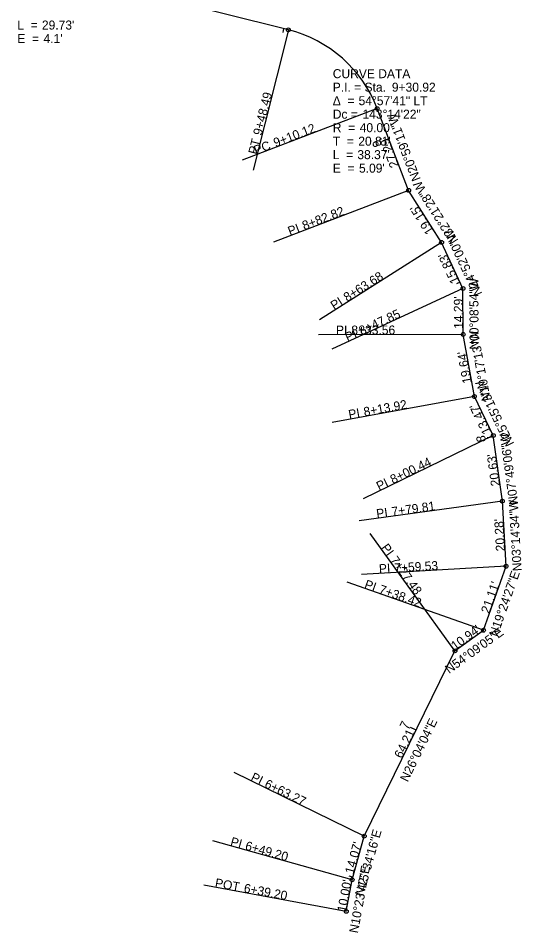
# Model space of a CAD drawing. Extents: x 1922742 to 1923057, y 359346 to 359870.
# Drawn here: x 1922900.4 to 1923056.9, y 359346.4 to 359631 of the extents above; entities that cross this region are included whole.
import ezdxf

# ---------------------------------------------------------------- set-up
doc = ezdxf.new("R2010")
doc.units = 0
for name, color, linetype in [('_CIVIL_CONSTRUCTION', 7, 'Continuous'), ('DT_P_Graded_Shoulder', 7, 'Continuous'), ('DT_P_Tie', 7, 'Continuous'), ('MD_P_ACB_B', 7, 'Continuous'), ('MD_P_ACSC_B', 7, 'Continuous'), ('MD_P_ACSC_T', 7, 'Continuous'), ('MD_P_AGB_T', 7, 'Continuous'), ('MD_P_AGST_B', 7, 'Continuous'), ('MD_P_AGST_T', 7, 'Continuous'), ('MD_P_GRADE_BREAK', 7, 'Continuous'), ('MD_P_PGL', 7, 'Continuous'), ('MD_P_Surface_Asphalt_Concrete_Base', 7, 'Continuous'), ('MD_X_XGL', 7, 'Continuous'), ('PV_P_EOP', 7, 'Continuous'), ('PV_P_Shoulder', 7, 'Continuous')]:
    doc.layers.add(name, color=color, linetype=linetype)

msp = doc.modelspace()

# ---------------------------------------------------------------- linework, layer by layer
at = {"layer": '_CIVIL_CONSTRUCTION'}
for p, q in [((1922984.36, 359627.36), (1922910.59, 359645.83)), ((1923021.77, 359577.4), (1923011.99, 359602.88)), ((1923032.01, 359561.23), (1923021.77, 359577.4)), ((1923038.67, 359546.87), (1923032.01, 359561.23)), ((1923038.71, 359532.58), (1923038.67, 359546.87)), ((1923042.21, 359513.25), (1923038.71, 359532.58)), ((1923048.1, 359501.13), (1923042.21, 359513.25)), ((1923050.91, 359480.69), (1923048.1, 359501.13)), ((1923052.06, 359460.45), (1923050.91, 359480.69)), ((1923045.04, 359440.54), (1923052.06, 359460.45)), ((1923036.17, 359434.13), (1923045.04, 359440.54)), ((1923007.96, 359376.45), (1923036.17, 359434.13)), ((1923004.18, 359362.9), (1923007.96, 359376.45)), ((1923002.38, 359353.06), (1923004.18, 359362.9))]:
    msp.add_line(p, q, dxfattribs=at)
msp.add_arc((1922974.65, 359588.56), 40, 20.9863, 75.9476, dxfattribs=at)
at = {"layer": 'MD_P_AGB_T'}
for p, q in [((1922984.36, 359627.36), (1922973.43, 359583.71)), ((1923011.99, 359602.88), (1922969.98, 359586.77)), ((1923021.77, 359577.4), (1922979.75, 359561.29)), ((1923032.01, 359561.23), (1922994, 359537.14)), ((1923038.67, 359546.87), (1922997.84, 359527.95)), ((1923038.71, 359532.58), (1922993.71, 359532.46)), ((1923042.21, 359513.25), (1922997.94, 359505.22)), ((1923048.1, 359501.13), (1923007.63, 359481.46)), ((1923050.91, 359480.69), (1923006.33, 359474.57)), ((1923036.17, 359434.13), (1923009.82, 359470.6)), ((1923052.06, 359460.45), (1923007.13, 359457.9)), ((1923045.04, 359440.54), (1923002.6, 359455.49)), ((1923007.96, 359376.45), (1922967.54, 359396.23)), ((1923004.18, 359362.9), (1922960.83, 359374.98)), ((1923002.38, 359353.06), (1922958.12, 359361.18))]:
    msp.add_line(p, q, dxfattribs=at)
for centre in [(1922984.36, 359627.36), (1923011.99, 359602.88), (1923021.77, 359577.4), (1923032.01, 359561.23), (1923038.67, 359546.87), (1923038.71, 359532.58), (1923042.21, 359513.25), (1923048.1, 359501.13), (1923050.91, 359480.69), (1923052.06, 359460.45), (1923045.04, 359440.54), (1923036.17, 359434.13), (1923007.96, 359376.45), (1923004.18, 359362.9), (1923002.38, 359353.06)]:
    msp.add_circle(centre, 0.6, dxfattribs=at)
at = {"layer": 'MD_P_AGST_B'}
for p, q in [((1922984.36, 359627.36), (1922973.43, 359583.71)), ((1923011.99, 359602.88), (1922969.98, 359586.77)), ((1923021.77, 359577.4), (1922979.75, 359561.29)), ((1923032.01, 359561.23), (1922994, 359537.14)), ((1923038.67, 359546.87), (1922997.84, 359527.95)), ((1923038.71, 359532.58), (1922993.71, 359532.46)), ((1923042.21, 359513.25), (1922997.94, 359505.22)), ((1923048.1, 359501.13), (1923007.63, 359481.46)), ((1923050.91, 359480.69), (1923006.33, 359474.57)), ((1923036.17, 359434.13), (1923009.82, 359470.6)), ((1923052.06, 359460.45), (1923007.13, 359457.9)), ((1923045.04, 359440.54), (1923002.6, 359455.49)), ((1923007.96, 359376.45), (1922967.54, 359396.23)), ((1923004.18, 359362.9), (1922960.83, 359374.98)), ((1923002.38, 359353.06), (1922958.12, 359361.18))]:
    msp.add_line(p, q, dxfattribs=at)
for centre in [(1922984.36, 359627.36), (1923011.99, 359602.88), (1923021.77, 359577.4), (1923032.01, 359561.23), (1923038.67, 359546.87), (1923038.71, 359532.58), (1923042.21, 359513.25), (1923048.1, 359501.13), (1923050.91, 359480.69), (1923052.06, 359460.45), (1923045.04, 359440.54), (1923036.17, 359434.13), (1923007.96, 359376.45), (1923004.18, 359362.9), (1923002.38, 359353.06)]:
    msp.add_circle(centre, 0.6, dxfattribs=at)
at = {"layer": 'MD_P_GRADE_BREAK'}
for p, q in [((1922984.36, 359627.36), (1922973.43, 359583.71)), ((1923011.99, 359602.88), (1922969.98, 359586.77)), ((1923021.77, 359577.4), (1922979.75, 359561.29)), ((1923032.01, 359561.23), (1922994, 359537.14)), ((1923038.67, 359546.87), (1922997.84, 359527.95)), ((1923038.71, 359532.58), (1922993.71, 359532.46)), ((1923042.21, 359513.25), (1922997.94, 359505.22)), ((1923048.1, 359501.13), (1923007.63, 359481.46)), ((1923050.91, 359480.69), (1923006.33, 359474.57)), ((1923036.17, 359434.13), (1923009.82, 359470.6)), ((1923052.06, 359460.45), (1923007.13, 359457.9)), ((1923045.04, 359440.54), (1923002.6, 359455.49)), ((1923007.96, 359376.45), (1922967.54, 359396.23)), ((1923004.18, 359362.9), (1922960.83, 359374.98)), ((1923002.38, 359353.06), (1922958.12, 359361.18))]:
    msp.add_line(p, q, dxfattribs=at)
for centre in [(1922984.36, 359627.36), (1923011.99, 359602.88), (1923021.77, 359577.4), (1923032.01, 359561.23), (1923038.67, 359546.87), (1923038.71, 359532.58), (1923042.21, 359513.25), (1923048.1, 359501.13), (1923050.91, 359480.69), (1923052.06, 359460.45), (1923045.04, 359440.54), (1923036.17, 359434.13), (1923007.96, 359376.45), (1923004.18, 359362.9), (1923002.38, 359353.06)]:
    msp.add_circle(centre, 0.6, dxfattribs=at)
at = {"layer": 'MD_P_Surface_Asphalt_Concrete_Base'}
for p, q in [((1923015.62, 359593.44), (1923014.49, 359593.01)), ((1923048.16, 359500.69), (1923046.98, 359500.53)), ((1923024.1, 359409.44), (1923023.02, 359409.97))]:
    msp.add_line(p, q, dxfattribs=at)
at = {"layer": 'MD_X_XGL'}
for p, q in [((1922982.89, 359627.73), (1922982.6, 359626.57)), ((1923015.62, 359593.44), (1923013.75, 359592.72)), ((1923037.77, 359548.82), (1923036.68, 359548.32)), ((1923048.16, 359500.69), (1923046.18, 359500.42)), ((1923048.89, 359451.46), (1923047.76, 359451.86)), ((1923024.1, 359409.44), (1923022.3, 359410.32)), ((1923004.4, 359363.67), (1923003.24, 359363.99))]:
    msp.add_line(p, q, dxfattribs=at)

# ---------------------------------------------------------------- texts
at = {"layer": 'DT_P_Graded_Shoulder'}
for s, p in [('L  = ', (1922900.06, 359627.45)), ("29.73'", (1922907.71, 359627.45)), ('E  = ', (1922900.06, 359623.25)), ("4.1'", (1922908.21, 359623.25)), ('CURVE DATA', (1922998.17, 359612.32)), ('P.I. = Sta. ', (1922998.17, 359608.12)), ('9+30.92', (1923016.54, 359608.12)), ('Δ  = ', (1922998.17, 359603.92)), ('54°57\'41" LT', (1923006.2, 359603.92)), ('Dc = ', (1922998.17, 359599.72)), ('143°14\'22"', (1923007.41, 359599.72)), ('R  = ', (1922998.17, 359595.52)), ("40.00'", (1923006.54, 359595.52)), ('T  = ', (1922998.17, 359591.32)), ("20.81'", (1923006.11, 359591.32)), ('L  = ', (1922998.17, 359587.12)), ("38.37'", (1923005.82, 359587.12)), ('E  = ', (1922998.17, 359582.92)), ("5.09'", (1923006.33, 359582.92))]:
    msp.add_text(s, height=2.8, dxfattribs=at).set_placement(p)
at = {"layer": 'DT_P_Tie'}
for s, rotation, p in [("27.29'", 110.9863, (1923018.77, 359585.09)), ("19.15'", 122.3578, (1923029.74, 359564.73)), ("15.83'", 114.8667, (1923037.57, 359549.13)), ("14.29'", 90.1483, (1923038.66, 359534.32)), ("19.64'", 100.2868, (1923041.38, 359517.59)), ("13.47'", 115.9204, (1923047.48, 359502.32)), ("20.63'", 97.8183, (1923050.2, 359485.56)), ("20.28'", 93.2428, (1923051.74, 359465.18)), ("21.11'", 70.5925, (1923046.81, 359445.54)), ("10.94'", 35.8487, (1923036.21, 359434.21)), ("64.21'", 63.9322, (1923019.65, 359400.46)), ("14.07'", 74.4288, (1923004.58, 359364.49)), ("10.00'", 79.6049, (1923002.26, 359352.68))]:
    msp.add_text(s, height=2.8, rotation=rotation, dxfattribs=at).set_placement(p)
at = {"layer": 'MD_P_ACB_B'}
for s, rotation, p in [("27.29'", 110.9863, (1923018.77, 359585.09)), ("19.15'", 122.3578, (1923029.74, 359564.73)), ("15.83'", 114.8667, (1923037.57, 359549.13)), ("14.29'", 90.1483, (1923038.66, 359534.32)), ("19.64'", 100.2868, (1923041.38, 359517.59)), ("13.47'", 115.9204, (1923047.48, 359502.32)), ("20.63'", 97.8183, (1923050.2, 359485.56)), ("20.28'", 93.2428, (1923051.74, 359465.18)), ("21.11'", 70.5925, (1923046.81, 359445.54)), ("10.94'", 35.8487, (1923036.21, 359434.21)), ("64.21'", 63.9322, (1923019.65, 359400.46)), ("14.07'", 74.4288, (1923004.58, 359364.49)), ("10.00'", 79.6049, (1923002.26, 359352.68))]:
    msp.add_text(s, height=2.8, rotation=rotation, dxfattribs=at).set_placement(p)
at = {"layer": 'MD_P_ACSC_B'}
for s, rotation, p in [('N20°59\'11"W', 110.9863, (1923025.56, 359580.92)), ('N32°21\'28"W', 122.3578, (1923037.3, 359561.86)), ('N24°52\'00"W', 114.8667, (1923044.69, 359545.3)), ('N00°08\'54"W', 90.1483, (1923043.52, 359527.87)), ('N10°17\'13"W', 100.2868, (1923047.3, 359512.1)), ('N25°55\'13"W', 115.9204, (1923054.66, 359498.62)), ('N07°49\'06"W', 97.8183, (1923055.88, 359479.81)), ('N03°14\'34"W', 93.2428, (1923056.95, 359458.99)), ('N19°24\'27"E', 70.5925, (1923049.36, 359438.35)), ('N54°09\'05"E', 35.8487, (1923034.36, 359426.89)), ('N26°04\'04"E', 63.9322, (1923021.47, 359393.14)), ('N15°34\'16"E', 74.4288, (1923007.69, 359357.62)), ('N10°23\'42"E', 79.6049, (1923005.98, 359346.12))]:
    msp.add_text(s, height=2.8, rotation=rotation, dxfattribs=at).set_placement(p)
at = {"layer": 'MD_P_ACSC_T'}
for s, p in [('L  = ', (1922900.06, 359627.45)), ("29.73'", (1922907.71, 359627.45)), ('E  = ', (1922900.06, 359623.25)), ("4.1'", (1922908.21, 359623.25)), ('CURVE DATA', (1922998.17, 359612.32)), ('P.I. = Sta. ', (1922998.17, 359608.12)), ('9+30.92', (1923016.54, 359608.12)), ('Δ  = ', (1922998.17, 359603.92)), ('54°57\'41" LT', (1923006.2, 359603.92)), ('Dc = ', (1922998.17, 359599.72)), ('143°14\'22"', (1923007.41, 359599.72)), ('R  = ', (1922998.17, 359595.52)), ("40.00'", (1923006.54, 359595.52)), ('T  = ', (1922998.17, 359591.32)), ("20.81'", (1923006.11, 359591.32)), ('L  = ', (1922998.17, 359587.12)), ("38.37'", (1923005.82, 359587.12)), ('E  = ', (1922998.17, 359582.92)), ("5.09'", (1923006.33, 359582.92))]:
    msp.add_text(s, height=2.8, dxfattribs=at).set_placement(p)
at = {"layer": 'MD_P_AGB_T'}
for s, rotation, p in [('9+48.49', 75.9476, (1922976.04, 359594.32)), ('9+10.12', 20.9863, (1922980.35, 359590.8)), ('PT', 75.9476, (1922974.56, 359588.42)), ('PC', 20.9863, (1922974.26, 359588.46)), ('8+82.82', 20.9863, (1922989.31, 359565)), ('PI', 20.9863, (1922984.85, 359563.29)), ('8+63.68', 32.3578, (1923002.64, 359542.67)), ('PI', 32.3578, (1922998.6, 359540.11)), ('8+47.85', 24.8667, (1923007.11, 359532.29)), ('PI', 0.1483, (1922999.17, 359532.52)), ('8+33.56', 0.1483, (1923003.95, 359532.53)), ('PI', 24.8667, (1923002.77, 359530.28)), ('8+13.92', 10.2868, (1923008.02, 359507.09)), ('PI', 10.2868, (1923003.32, 359506.24)), ('8+00.44', 25.9204, (1923016.87, 359486)), ('PI', 25.9204, (1923012.57, 359483.91)), ('PI', 7.8183, (1923011.91, 359475.38)), ('7+79.81', 7.8183, (1923016.65, 359476.03)), ('PI', 305.8487, (1923013.06, 359466.2)), ('7+27.48', 305.8487, (1923015.86, 359462.32)), ('7+59.53', 3.2428, (1923017.38, 359458.53)), ('PI', 3.2428, (1923012.6, 359458.26)), ('PI', 340.5925, (1923007.78, 359453.71)), ('7+38.42', 340.5925, (1923012.29, 359452.13)), ('PI', 333.9322, (1922972.42, 359393.89)), ('6+63.27', 333.9322, (1922976.71, 359391.79)), ('PI', 344.4288, (1922966.11, 359373.55)), ('6+49.20', 344.4288, (1922970.72, 359372.27)), ('POT', 349.6049, (1922961.37, 359360.63)), ('6+39.20', 349.6049, (1922970.35, 359358.99))]:
    msp.add_text(s, height=2.8, rotation=rotation, dxfattribs=at).set_placement(p)
at = {"layer": 'MD_P_AGST_B'}
for s, rotation, p in [('9+48.49', 75.9476, (1922976.04, 359594.32)), ('9+10.12', 20.9863, (1922980.35, 359590.8)), ('PT', 75.9476, (1922974.56, 359588.42)), ('PC', 20.9863, (1922974.26, 359588.46)), ('8+82.82', 20.9863, (1922989.31, 359565)), ('PI', 20.9863, (1922984.85, 359563.29)), ('8+63.68', 32.3578, (1923002.64, 359542.67)), ('PI', 32.3578, (1922998.6, 359540.11)), ('8+47.85', 24.8667, (1923007.11, 359532.29)), ('PI', 0.1483, (1922999.17, 359532.52)), ('8+33.56', 0.1483, (1923003.95, 359532.53)), ('PI', 24.8667, (1923002.77, 359530.28)), ('8+13.92', 10.2868, (1923008.02, 359507.09)), ('PI', 10.2868, (1923003.32, 359506.24)), ('8+00.44', 25.9204, (1923016.87, 359486)), ('PI', 25.9204, (1923012.57, 359483.91)), ('PI', 7.8183, (1923011.91, 359475.38)), ('7+79.81', 7.8183, (1923016.65, 359476.03)), ('PI', 305.8487, (1923013.06, 359466.2)), ('7+27.48', 305.8487, (1923015.86, 359462.32)), ('7+59.53', 3.2428, (1923017.38, 359458.53)), ('PI', 3.2428, (1923012.6, 359458.26)), ('PI', 340.5925, (1923007.78, 359453.71)), ('7+38.42', 340.5925, (1923012.29, 359452.13)), ('PI', 333.9322, (1922972.42, 359393.89)), ('6+63.27', 333.9322, (1922976.71, 359391.79)), ('PI', 344.4288, (1922966.11, 359373.55)), ('6+49.20', 344.4288, (1922970.72, 359372.27)), ('POT', 349.6049, (1922961.37, 359360.63)), ('6+39.20', 349.6049, (1922970.35, 359358.99))]:
    msp.add_text(s, height=2.8, rotation=rotation, dxfattribs=at).set_placement(p)
at = {"layer": 'MD_P_AGST_T'}
for s, p in [('L  = ', (1922900.06, 359627.45)), ("29.73'", (1922907.71, 359627.45)), ('E  = ', (1922900.06, 359623.25)), ("4.1'", (1922908.21, 359623.25)), ('CURVE DATA', (1922998.17, 359612.32)), ('P.I. = Sta. ', (1922998.17, 359608.12)), ('9+30.92', (1923016.54, 359608.12)), ('Δ  = ', (1922998.17, 359603.92)), ('54°57\'41" LT', (1923006.2, 359603.92)), ('Dc = ', (1922998.17, 359599.72)), ('143°14\'22"', (1923007.41, 359599.72)), ('R  = ', (1922998.17, 359595.52)), ("40.00'", (1923006.54, 359595.52)), ('T  = ', (1922998.17, 359591.32)), ("20.81'", (1923006.11, 359591.32)), ('L  = ', (1922998.17, 359587.12)), ("38.37'", (1923005.82, 359587.12)), ('E  = ', (1922998.17, 359582.92)), ("5.09'", (1923006.33, 359582.92))]:
    msp.add_text(s, height=2.8, dxfattribs=at).set_placement(p)
at = {"layer": 'MD_P_GRADE_BREAK'}
for s, rotation, p in [('9+48.49', 75.9476, (1922976.04, 359594.32)), ('9+10.12', 20.9863, (1922980.35, 359590.8)), ('PT', 75.9476, (1922974.56, 359588.42)), ('PC', 20.9863, (1922974.26, 359588.46)), ('8+82.82', 20.9863, (1922989.31, 359565)), ('PI', 20.9863, (1922984.85, 359563.29)), ('8+63.68', 32.3578, (1923002.64, 359542.67)), ('PI', 32.3578, (1922998.6, 359540.11)), ('8+47.85', 24.8667, (1923007.11, 359532.29)), ('PI', 0.1483, (1922999.17, 359532.52)), ('8+33.56', 0.1483, (1923003.95, 359532.53)), ('PI', 24.8667, (1923002.77, 359530.28)), ('8+13.92', 10.2868, (1923008.02, 359507.09)), ('PI', 10.2868, (1923003.32, 359506.24)), ('8+00.44', 25.9204, (1923016.87, 359486)), ('PI', 25.9204, (1923012.57, 359483.91)), ('PI', 7.8183, (1923011.91, 359475.38)), ('7+79.81', 7.8183, (1923016.65, 359476.03)), ('PI', 305.8487, (1923013.06, 359466.2)), ('7+27.48', 305.8487, (1923015.86, 359462.32)), ('7+59.53', 3.2428, (1923017.38, 359458.53)), ('PI', 3.2428, (1923012.6, 359458.26)), ('PI', 340.5925, (1923007.78, 359453.71)), ('7+38.42', 340.5925, (1923012.29, 359452.13)), ('PI', 333.9322, (1922972.42, 359393.89)), ('6+63.27', 333.9322, (1922976.71, 359391.79)), ('PI', 344.4288, (1922966.11, 359373.55)), ('6+49.20', 344.4288, (1922970.72, 359372.27)), ('POT', 349.6049, (1922961.37, 359360.63)), ('6+39.20', 349.6049, (1922970.35, 359358.99))]:
    msp.add_text(s, height=2.8, rotation=rotation, dxfattribs=at).set_placement(p)
at = {"layer": 'MD_P_PGL'}
for s, rotation, p in [("27.29'", 110.9863, (1923018.77, 359585.09)), ("19.15'", 122.3578, (1923029.74, 359564.73)), ("15.83'", 114.8667, (1923037.57, 359549.13)), ("14.29'", 90.1483, (1923038.66, 359534.32)), ("19.64'", 100.2868, (1923041.38, 359517.59)), ("13.47'", 115.9204, (1923047.48, 359502.32)), ("20.63'", 97.8183, (1923050.2, 359485.56)), ("20.28'", 93.2428, (1923051.74, 359465.18)), ("21.11'", 70.5925, (1923046.81, 359445.54)), ("10.94'", 35.8487, (1923036.21, 359434.21)), ("64.21'", 63.9322, (1923019.65, 359400.46)), ("14.07'", 74.4288, (1923004.58, 359364.49)), ("10.00'", 79.6049, (1923002.26, 359352.68))]:
    msp.add_text(s, height=2.8, rotation=rotation, dxfattribs=at).set_placement(p)
at = {"layer": 'MD_X_XGL'}
for s, rotation, p in [('9', 110.9863, (1923013.62, 359591.52)), ('8', 97.8183, (1923045.79, 359499.26)), ('7', 63.9322, (1923021.34, 359409.5))]:
    msp.add_text(s, height=2.8, rotation=rotation, dxfattribs=at).set_placement(p)
at = {"layer": 'PV_P_EOP'}
for s, rotation, p in [('N20°59\'11"W', 110.9863, (1923025.56, 359580.92)), ('N32°21\'28"W', 122.3578, (1923037.3, 359561.86)), ('N24°52\'00"W', 114.8667, (1923044.69, 359545.3)), ('N00°08\'54"W', 90.1483, (1923043.52, 359527.87)), ('N10°17\'13"W', 100.2868, (1923047.3, 359512.1)), ('N25°55\'13"W', 115.9204, (1923054.66, 359498.62)), ('N07°49\'06"W', 97.8183, (1923055.88, 359479.81)), ('N03°14\'34"W', 93.2428, (1923056.95, 359458.99)), ('N19°24\'27"E', 70.5925, (1923049.36, 359438.35)), ('N54°09\'05"E', 35.8487, (1923034.36, 359426.89)), ('N26°04\'04"E', 63.9322, (1923021.47, 359393.14)), ('N15°34\'16"E', 74.4288, (1923007.69, 359357.62)), ('N10°23\'42"E', 79.6049, (1923005.98, 359346.12))]:
    msp.add_text(s, height=2.8, rotation=rotation, dxfattribs=at).set_placement(p)
at = {"layer": 'PV_P_Shoulder'}
for s, rotation, p in [('N20°59\'11"W', 110.9863, (1923025.56, 359580.92)), ('N32°21\'28"W', 122.3578, (1923037.3, 359561.86)), ('N24°52\'00"W', 114.8667, (1923044.69, 359545.3)), ('N00°08\'54"W', 90.1483, (1923043.52, 359527.87)), ('N10°17\'13"W', 100.2868, (1923047.3, 359512.1)), ('N25°55\'13"W', 115.9204, (1923054.66, 359498.62)), ('N07°49\'06"W', 97.8183, (1923055.88, 359479.81)), ('N03°14\'34"W', 93.2428, (1923056.95, 359458.99)), ('N19°24\'27"E', 70.5925, (1923049.36, 359438.35)), ('N54°09\'05"E', 35.8487, (1923034.36, 359426.89)), ('N26°04\'04"E', 63.9322, (1923021.47, 359393.14)), ('N15°34\'16"E', 74.4288, (1923007.69, 359357.62)), ('N10°23\'42"E', 79.6049, (1923005.98, 359346.12))]:
    msp.add_text(s, height=2.8, rotation=rotation, dxfattribs=at).set_placement(p)

doc.saveas('drawing.dxf')
